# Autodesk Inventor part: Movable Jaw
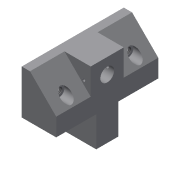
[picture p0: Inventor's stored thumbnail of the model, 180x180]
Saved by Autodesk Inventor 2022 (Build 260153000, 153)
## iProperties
Created: 2002-02
Part Number: Movable Jaw
Document SubType Name: Modeling
Designer: ***
Density: 1 g/cm^3
Material: Generic
Mass: 56.5588 g
Surface Area: 124.299 cm^2
Volume: 56.5588 cm^3
Appearance: Default
Control State: 0
Master: False
Checked Out: False
Shininess: 77.0
Length Units: 11269
Angle Units: 11279
Time Units: 11290
Mass Units: 11283
Length Display Precision: 3
Angle Display Precision: 2
Density: 0.0
Volumn: 0.0
Area: 0.0
PropertySet Name: Model Information
Author: ***
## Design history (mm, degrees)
sketch "Sketch2"
  geometry: L1 (2.39, 41.509)-(2.39, 9.509); L2 (2.39, 9.509)-(-22.61, 9.509); L3 (-22.61, 9.509)-(-22.61, 22.509); L4 (-22.61, 22.509)-(-3.61, 41.509); L5 (-3.61, 41.509)-(2.39, 41.509)
  constraints: 10 end point, 2 parallel, 1 perpendicular, 1 vertical
  dimensions: "d0" = 25 distance of L1.end L2.end; "d2" = 13 distance of L2.end L3.end; "d3" = 32 distance between parallel lines of L5 L2; "d4" = 6 distance of L4.end L1.start
extrude "Extrusion1" new body sketch "Sketch2" stored distance "d5" = 74; taper "d6" = 0 deg
sketch "Sketch3"
  geometry: L1 (-19, 25)-(11, 25); L2 (11, 25)-(11, 49); L3 (11, 49)-(-19, 49); L4 (-19, 49)-(-19, 25); L5 (0, 0)-(13, 0) reference; L6 (-19, 74)-(-19, 0) reference; L7 (11.924, 29)-(35, 29); L8 (35, 29)-(35, 45); L9 (35, 45)-(11.924, 45); L10 (11.924, 45)-(11.924, 29); L11 (13, 74)-(13, 0) reference
  constraints: 16 end point, 4 parallel, 2 horizontal, 2 perpendicular, 1 collinear
  dimensions: "d7" = 24 distance of L3.end L1.start; "d8" = 30 distance of L1.start L1.end; "d9" = 25 distance between parallel lines of L5 L1; "d10" = 16 distance of L7.end L8.end; "d11" = 4 distance between parallel lines of L3 L9; "d12" = 22 distance between parallel lines of L11 L8
extrude "Extrusion2" join sketch "Sketch3" distance "d13" = 25; taper "d14" = 0 deg
sketch "Sketch4"
  geometry: L1 (-19, -25)-(-19, -49) reference; L2 (-19, -49)-(0, -49) reference; 1 further point
  dimensions: "d15" = 11 distance from line of L1 point (-8, -37); "d16" = 12 distance from line of L2 point (-8, -37)
hole "Hole1" sketch "Sketch4" at (-8, -37) diameter "d17" = 10; stored, may be unused: countersink angle "d21" = 82 deg, drill point angle "d23" = 0 deg; dims "d18" = 6, "d19" = 4, "d20" = 2, "d22" = 13
sketch "Sketch5"
  geometry: L1 (-19, -49)-(-19, -74) reference; L2 (0, -74)-(13, -74) reference; 1 further point
  dimensions: "d24" = 14 distance from line of L1 point (-5, -62); "d25" = 12 distance from line of L2 point (-5, -62)
hole "Hole2" sketch "Sketch5" at (-5, -62) diameter "d26" = 4.917; stored, may be unused: countersink angle "d30" = 82 deg, drill point angle "d32" = 0 deg; dims "d27" = 12, "d28" = 8, "d29" = 10, "d31" = 17.1
mirror "Mirror1"
sketch "Sketch6"
  geometry: L1 (0, 19)-(0, 0) reference; 1 further point
  dimensions: "d33" = 5 distance from line of L1 point (-5, 8); "d34" = 11 vertical distance of L1.start point (-5, 8)
hole "Hole3" sketch "Sketch6" at (-5, 8) diameter "d35" = 2; stored, may be unused: countersink angle "d39" = 82 deg, drill point angle "d41" = 0 deg; dims "d36" = 6, "d37" = 8, "d38" = 10, "d40" = 13
body "Solid1"
